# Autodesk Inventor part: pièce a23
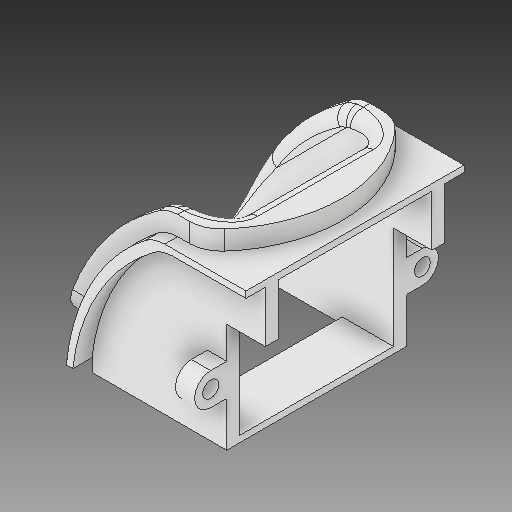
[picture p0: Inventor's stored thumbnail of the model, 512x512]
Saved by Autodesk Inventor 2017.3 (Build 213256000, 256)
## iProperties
Created: 2007-12
Part Number: pièce a23
Material: solidworks materials|PVC 0.007 plastifié|45
Document SubType Name: Modeling
Designer: ficho
Density: 1.29 g/cm^3
Appearance: 255,255,255
Author: ficho
Sending System: SolidWorks 2009
Last Author: christophe
Last Saved: 2011-02-10
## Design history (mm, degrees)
feature "Congé22"
node "Solide1"
